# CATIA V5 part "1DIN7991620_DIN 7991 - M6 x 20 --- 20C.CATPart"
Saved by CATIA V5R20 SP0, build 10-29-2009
Part number: 1DIN7991620_DIN 7991 - M6 x 20 --- 20C
Revision: ANY
Definition: UNKNOWN
Nomenclature: 1DIN7991620_DIN 7991 - M6 x 20 --- 20C
Source: Unknown
Bounding box of the stored display mesh (mm): x 0 to 20, y -5.785 to 5.785, z -5.785 to 5.785
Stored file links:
  C:\Users\Utente\Desktop\IO LAVORO\3D X SITO CF\CUMSA\3D files RC\RC 164008\1DIN7991620_DIN 7991 - M6 x 20 --- 20C.CATPart
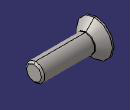
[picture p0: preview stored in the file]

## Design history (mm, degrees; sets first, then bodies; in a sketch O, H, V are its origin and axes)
Body1 "Hex" (main body)
  Solid1: solid without history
